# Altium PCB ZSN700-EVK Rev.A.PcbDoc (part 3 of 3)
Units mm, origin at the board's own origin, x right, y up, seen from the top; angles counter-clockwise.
Board outline 122.05 x 75.06 mm, 2 copper layers (Top Layer, Bottom Layer), stack 0 mm thick; 172 components, 135 nets, 573 pads, 599 vias.
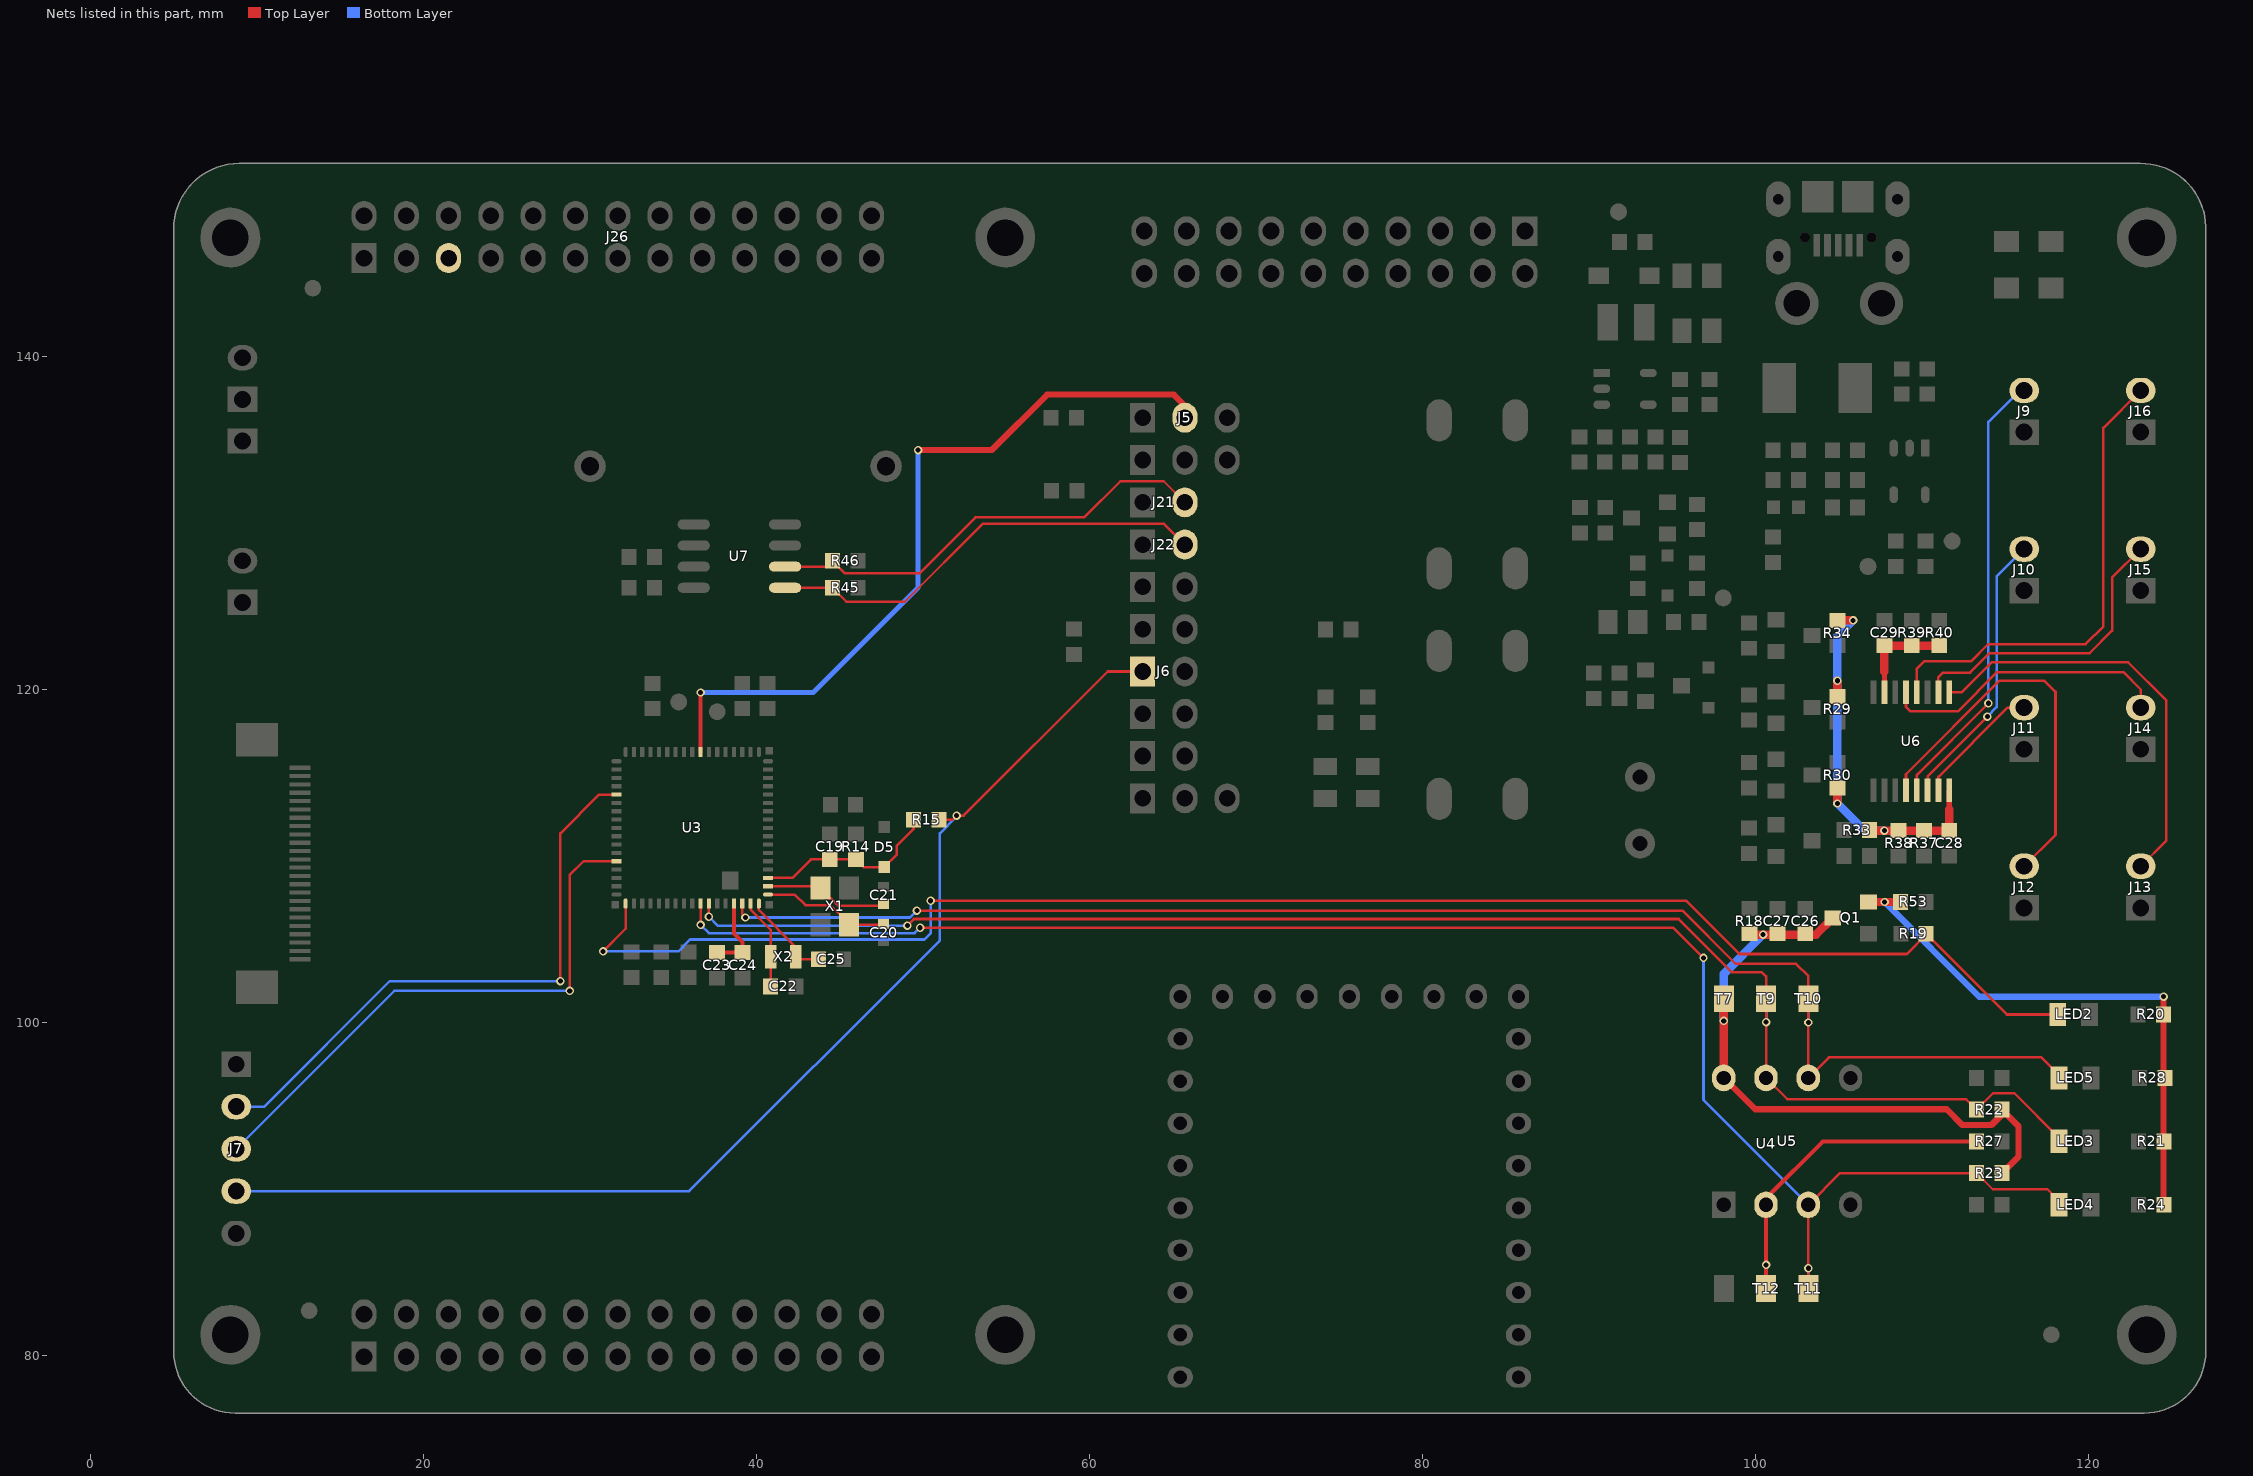
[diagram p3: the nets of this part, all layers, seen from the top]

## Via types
v1: diameter 0.508, hole 0.305, Top Layer to Bottom Layer, tented both sides, 599 vias

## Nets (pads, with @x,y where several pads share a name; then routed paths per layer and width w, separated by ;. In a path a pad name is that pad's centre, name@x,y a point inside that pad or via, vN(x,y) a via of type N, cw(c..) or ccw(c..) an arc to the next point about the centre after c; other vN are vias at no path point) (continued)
NRST: C19.1 D5.1 R14.1 R15.1 U3.37 | length 11.2
  Top Layer w0.152: U3.37@40.69,108.702 42.16,108.702 43.266,109.808 C19.1@44.399,109.808 R14.1@45.974,109.808 46.433,109.349 D5.1@47.676,109.349 48.438,110.111 48.438,110.636 49.44,111.639 R15.1@49.44,112.193
PB08: LED4.2 R23.1 T11.1 U3.27 U4.4 U5.3 | length 103.1
  Top Layer w0.152: v1(36.643,105.88) U3.27@36.643,107.152 ; v1(49.824,105.705) 95.078,105.705 v1(96.881,103.901) ; U4.4@103.178,84.037 v1(103.178,85.258) 103.178,89.063 U5.3@103.175,89.066 105.08,90.971 R23.1@113.284,90.971 114.254,90.001 117.529,90.001 118.237,89.293 LED4.2@118.237,89.066
  Bottom Layer w0.152: v1(36.643,105.88) 37.141,105.382 49.502,105.382 v1(49.824,105.705) ; v1(96.881,103.901) 96.881,95.36 U5.3@103.175,89.066 ; T11.1@103.178,84.037 v1(103.178,85.258)
PB09: LED3.2 R22.1 T9.1 U3.28 U4.2 U5.7 | length 93.7
  Top Layer w0.152: v1(37.143,106.369) U3.28@37.143,107.152 ; v1(49.062,105.84) 49.455,106.232 95.385,106.232 98.585,103.032 100.392,103.032 100.638,102.786 U4.2@100.638,101.437 v1(100.638,100.04) 100.638,96.69 U5.7@100.635,96.686 101.915,95.406 112.66,95.406 R22.1@113.284,94.781 114.27,95.767 115.548,95.767 118.237,93.078 LED3.2@118.237,92.876
  Bottom Layer w0.152: v1(37.143,106.369) 37.672,105.84 v1(49.062,105.84) ; v1(100.638,100.04) T9.1@100.638,101.437
PC13: LED5.2 T10.1 U3.32 U4.3 U5.6 | length 90.3
  Top Layer w0.152: U3.32@39.143,107.152 39.143,106.513 v1(39.334,106.322) ; v1(49.637,106.74) 95.617,106.74 98.818,103.54 102.45,103.54 103.178,102.811 U4.3@103.178,101.437 v1(103.178,100.015) U5.6@103.178,96.69 ; U5.6@103.175,96.686 U5.6@103.178,96.69 ; LED5.2@118.237,96.686 118.237,96.863 117.179,97.921 104.41,97.921 U5.6@103.178,96.69
  Bottom Layer w0.152: v1(39.334,106.322) 49.219,106.322 v1(49.637,106.74) ; v1(103.178,100.015) T10.1@103.178,101.437
PD02: LED2.2 R19.1 U3.18 | length 97.1
  Top Layer w0.152: v1(30.789,104.29) 32.143,105.645 U3.18@32.143,107.152 ; v1(50.459,107.33) 95.84,107.33 99.04,104.13 109.099,104.13 110.254,105.285 R19.1@110.254,105.349 115.107,100.496 LED2.2@118.161,100.496
  Bottom Layer w0.152: v1(30.789,104.29) 35.31,104.29 36.021,105.001 50.087,105.001 50.459,105.374 v1(50.459,107.33)
PVPP: R27.2 T12.1 U4.5 U5.2 | length 20.9
  Top Layer w0.152: U5.2@100.635,89.066 U5.2@100.638,89.063
  Top Layer w0.254: U5.2@100.635,89.066 100.635,89.463 104.049,92.876 R27.2@113.284,92.876 ; U4.5@100.638,84.037 v1(100.638,85.461) U5.2@100.638,89.063
  Bottom Layer w0.254: T12.1@100.638,84.037 v1(100.638,85.461)
RESETB: J6.1 J7.4 R15.2 | length 72.3
  Top Layer w0.152: R15.2@50.964,112.193 51.765,112.193 v1(52.019,112.447) 52.446,112.447 61.098,121.098 J6.1@63.191,121.098
  Bottom Layer w0.152: J7.4@8.755,89.886 35.956,89.886 51.015,104.945 51.015,111.38 52.019,112.384 v1(52.019,112.447)
RUN_AWORKS: J26.5
SAM_VCC: C26.1 C27.1 Q1.3 R18.1 R22.2 R23.2 T7.1 U4.1 U5.8 | length 39.4
  Top Layer w0.381: U5.8@98.095,96.686 99.985,94.797 111.481,94.797 112.415,93.862 114.177,93.862 114.808,94.494 R22.2@114.808,94.781 115.799,93.791 115.799,91.962 R23.2@114.808,90.971
  Top Layer w0.508: U5.8@98.095,96.686 98.098,96.69 v1(98.098,100.117) U4.1@98.098,101.437 ; R18.1@99.64,105.298 v1(100.463,105.298) 103.643,105.298 Q1.3@104.644,106.299
  Bottom Layer w0.508: v1(98.098,100.117) T7.1@98.098,101.437 98.098,102.934 v1(100.463,105.298)
SCL: J21.2 R46.1 U7.2 | length 27.3
  Top Layer w0.152: U7.2@41.723,127.394 44.212,127.394 R46.1@44.568,127.75 45.327,126.99 49.795,126.99 53.156,130.351 59.684,130.351 61.859,132.526 64.464,132.526 J21.2@65.731,131.258
SDA: J22.2 R45.1 U7.1 | length 26.8
  Top Layer w0.152: U7.1@41.723,126.124 R45.1@44.568,126.124 45.404,125.288 48.906,125.288 53.579,129.96 64.49,129.96 J22.2@65.731,128.718
SWCLK: J7.3 U3.13 | length 34.1
  Top Layer w0.152: v1(28.784,101.916) 28.784,108.873 29.613,109.702 U3.13@31.59,109.702
  Bottom Layer w0.152: J7.3@8.755,92.426 18.246,101.916 v1(28.784,101.916)
SWDIO: J7.2 U3.5 | length 35.8
  Top Layer w0.152: v1(28.225,102.496) 28.225,111.375 30.553,113.702 U3.5@31.59,113.702
  Bottom Layer w0.152: J7.2@8.755,94.966 10.446,94.966 17.976,102.496 v1(28.225,102.496)
TX1: J9.2 U6.13 | length 26.8
  Top Layer w0.152: U6.13@109.693,113.956 109.693,114.89 v1(113.995,119.191)
  Bottom Layer w0.152: v1(113.995,119.191) 113.995,136.082 115.889,137.977 J9.2@116.143,137.977
TX2: J10.2 U6.14 | length 16.9
  Top Layer w0.152: U6.14@110.343,113.956 110.343,114.804 v1(113.933,118.393)
  Bottom Layer w0.152: v1(113.933,118.393) 114.492,118.952 114.492,126.8 J10.2@116.143,128.451
TX3: J11.2 U6.15 | length 7.7
  Top Layer w0.152: U6.15@110.993,113.956 110.993,114.768 115.151,118.925 J11.2@116.143,118.925
TX4: J12.2 U6.12 | length 23.8
  Top Layer w0.152: U6.12@109.043,113.956 109.043,114.926 114.67,120.552 117.339,120.552 118.022,119.869 118.022,111.279 J12.2@116.143,109.4
TX5: J13.2 U6.1 | length 25.3
  Top Layer w0.152: U6.1@111.643,119.856 112.398,119.856 114.187,121.645 122.391,121.645 124.677,119.359 124.677,110.934 J13.2@123.143,109.4
TX6: J14.2 U6.5 | length 17.6
  Top Layer w0.152: U6.5@109.043,119.856 109.043,118.978 109.323,118.698 112.155,118.698 114.517,121.06 122.098,121.06 123.143,120.015 J14.2@123.143,118.925
TX7: J15.2 U6.2 | length 18.1
  Top Layer w0.152: U6.2@110.993,119.856 110.993,120.762 111.266,121.035 112.892,121.035 114.06,122.203 120.08,122.203 121.426,123.55 121.426,126.734 J15.2@123.143,128.451
TX8: J16.2 U6.4 | length 28.8
  Top Layer w0.152: U6.4@109.693,119.856 109.693,121.269 110.127,121.703 112.95,121.703 113.984,122.737 119.826,122.737 120.893,123.804 120.893,135.727 J16.2@123.143,137.977
VCAP: C23.1 C24.1 U3.31 | length 4.7
  Top Layer w0.254: C23.1@37.639,104.226 C24.1@39.163,104.226 39.163,104.842 38.643,105.362 U3.31@38.643,107.152
VCC_4051: C28.1 R29.2 R30.2 R33.2 R34.2 R37.2 R38.2 U6.16 | length 24.9
  Top Layer w0.305: 111.643,112.817 U6.16@111.643,113.956
  Top Layer w0.508: v1(104.923,113.17) R30.2@104.923,114.112 ; R29.2@104.923,119.598 v1(104.923,120.54) ; R34.2@104.923,124.17 v1(105.865,124.17) ; R33.2@106.856,111.572 106.885,111.543 v1(107.74,111.543) R38.2@108.595,111.543 R37.2@110.119,111.543 C28.1@111.643,111.543 111.643,112.817
  Bottom Layer w0.508: v1(105.865,124.17) 104.923,123.229 v1(104.923,120.54) v1(104.923,113.17) 106.551,111.543 v1(107.74,111.543)
VCC_ANT: J5.2 U3.59 | length 45.9
  Top Layer w0.254: U3.59@36.643,116.252 v1(36.643,119.837)
  Top Layer w0.381: v1(49.713,134.398) 54.125,134.398 57.457,137.73 65.059,137.73 65.731,137.058 J5.2@65.731,136.338
  Bottom Layer w0.305: v1@36.624,119.837 v1(36.643,119.837) 43.405,119.837 49.713,126.146 v1(49.713,134.398)
VDD_3V3_SAM: Q1.2 R20.2 R21.2 R24.2 R28.2 R53.2 | length 33.5
  Top Layer w0.381: R24.2@124.512,89.1 R20.2@124.512,100.496 v1(124.512,101.57)
  Top Layer w0.508: Q1.2@106.803,107.249 106.808,107.254 v1(107.758,107.254) R53.2@108.708,107.254 ; R24.2@124.512,89.1 R24.2@124.546,89.066
  Bottom Layer w0.381: v1(107.758,107.254) 113.442,101.57 v1(124.512,101.57)
VEE_4051: C29.1 R39.2 R40.2 U6.7 | length 6.1
  Top Layer w0.305: U6.7@107.743,119.856 107.743,121.096
  Top Layer w0.508: 107.743,121.096 C29.1@107.743,122.65 R39.2@109.394,122.65 R40.2@111.045,122.65
XTHI: C20.2 U3.35 X1.1 | length 7.8
  Top Layer w0.152: U3.35@40.69,107.702 42.298,107.702 42.939,107.061 44.43,107.061 X1.1@45.599,105.892 ; X1.1@45.549,105.892 X1.1@45.599,105.892 ; X1.1@45.664,105.888 45.603,105.888 X1.1@45.599,105.892 ; C20.2@47.631,105.918 47.605,105.892 X1.1@45.599,105.892
XTHO: C21.1 U3.36 X1.3 | length 7.6
  Top Layer w0.152: U3.36@40.69,108.202 43.739,108.202 X1.3@43.849,108.092 X1.3@43.854,108.088 ; X1.3@43.964,108.088 X1.3@43.854,108.088 ; C21.1@47.631,107.137 47.529,107.035 44.906,107.035 X1.3@43.854,108.088
XTLI: C22.1 U3.33 X2.2 | length 5.5
  Top Layer w0.152: U3.33@39.643,107.152 39.643,106.796 40.851,105.588 X2.2@40.851,103.973 40.855,103.969 C22.1@40.855,102.185
XTLO: C25.1 U3.34 X2.1 | length 5.5
  Top Layer w0.152: U3.34@40.143,107.152 40.143,106.763 42.351,104.555 X2.1@42.351,103.973 42.515,103.81 C25.1@43.719,103.81
pads on no net: HOLE1.1 HOLE2.1 HOLE3.1 HOLE5.1 HOLE6.1 J1.0 J1.2 J1.3 J1.4 J28.13 J28.14 J28.15 J28.16 J28.17 J28.18 J28.19 J28.20 J28.21 J28.22 J28.23 J28.24 MARK3.0 MARK4.0 MARK5.0 U3. U7.3
copper on no net:
  other v1: 0,151.614

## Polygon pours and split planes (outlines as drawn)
GND on Top Layer "GND" (solid, remove dead copper, pour order 0): 5,80.24 ccw(c8.683,80.24) 8.683,76.557 123.364,76.557 ccw(c123.364,80.24) 127.047,80.24 127.047,147.804 ccw(c123.174,147.74) 123.11,151.614 8.937,151.614 ccw(c8.937,147.677) 5,147.677
GND on Bottom Layer "GND" (solid, remove dead copper, pour order 2): 5,80.24 ccw(c8.683,80.24) 8.683,76.557 123.364,76.557 ccw(c123.364,80.24) 127.047,80.24 127.047,147.804 ccw(c123.174,147.74) 123.11,151.614 8.937,151.614 ccw(c8.937,147.677) 5,147.677

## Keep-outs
Keep-Out Layer:
  the board outline again, w0.127

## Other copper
Top Layer:
  rectangle net GND: 106.756,126.668 111.582,127.994
  pour cut-out: 108.307,134.512 110.207,134.512 110.207,136.224 108.307,136.224
  pour cut-out: 95.885,143.768 95.885,142.625 96.85,142.625 96.85,143.768
  pour cut-out: 92.982,138.383 91.491,138.383 91.237,138.637 91.323,138.637 91.752,139.066 92.688,139.066 92.982,138.772
  pour cut-out: 119.092,101.577 119.092,99.415 119.23,99.415 119.23,101.577
  pour cut-out: 119.125,90.147 119.125,87.985 119.263,87.985 119.263,90.147
  pour cut-out: 119.125,93.957 119.125,91.795 119.263,91.795 119.263,93.957
  pour cut-out: 119.125,97.767 119.125,95.605 119.263,95.605 119.263,97.767
  region net GND: 109.168,126.289 108.788,126.668 106.756,126.668 106.756,127.994 111.582,127.994 111.582,126.367 111.504,126.289
  pour cut-out: 73.091,116.269 77.793,116.269 77.793,114.355 73.091,114.355
  pour cut-out: 94.281,120.357 94.281,119.892 94.005,119.892 94.005,120.357
  pour cut-out: 104.067,121.815 101.905,121.815 101.905,122.432 104.067,122.432
  pour cut-out: 102.129,119.05 102.129,116.437 101.651,116.437 101.651,119.05
  pour cut-out: 102.129,114.986 101.6,114.986 101.6,112.729 102.129,112.729
  pour cut-out: 102.51,111.775 102.51,111.256 101.879,111.256 101.879,111.775
  pour cut-out: 112.453,90.505 112.878,90.505 112.878,89.412 112.453,89.412
  region net 5.0V_AWORKS: 109.953,135.426 108.505,136.874 108.505,138.181 110.703,138.181 110.994,137.89 110.994,134.283 110.715,134.004 109.953,134.004
  region net 3.3V: 109.699,130.132 109.179,129.612 109.179,128.529 109.343,128.365 110.709,128.365 110.918,128.575 110.918,132.208 110.664,132.462 109.935,132.462 109.699,132.226
  region net 5.0V_AWORKS: 106.071,146.801 106.071,142.889 107.023,141.937 108.255,143.168 108.255,144.311 106.477,146.089 106.477,146.801
  region net 5.0V_AWORKS: 107.874,144.692 104.928,141.746 104.928,136.692 104.982,136.638 107.161,136.638 107.341,136.818 107.341,140.73 109.043,142.432 109.043,143.524
  region net GND: 103.877,146.801 103.877,142.575 101.969,140.666 100.661,141.975 100.661,143.279 103.471,146.089 103.471,146.801
  region net NetC10_1: 92.702,139.052 92.982,138.772 94.186,138.772 94.821,138.137 97.797,138.137 97.899,138.238 97.899,139.544 97.757,139.686 96.766,139.686 96.258,140.194 96.258,142.189 96.157,142.291 92.919,142.291 92.702,142.074
  region net -5V_IN: 91.752,139.066 91.483,138.797 89.934,138.797 89.705,139.026 89.705,145.376 89.832,145.503 91.559,145.503 91.752,145.31
  region net NetC8_1: 92.906,145.909 92.906,147.56 96.081,147.56 96.208,147.433 96.208,144.131 96.081,144.004 93.083,144.004 92.906,144.182
  region net 8V: 92.131,148.017 92.36,147.789 92.36,146.265 92.131,146.036 90.455,146.036 90.455,148.017
Bottom Layer:
  pour cut-out: 62.06,112.783 62.06,111.174 63.123,111.174 63.123,112.783
Multi-Layer:
  pour cut-out: 99.06,151.614 99.06,141.482 99.72,140.821 111.023,140.821 111.506,141.304 111.506,144.377 111.897,144.769 118.898,144.769 120.904,142.762 127.047,142.762 127.047,149.918 125.351,151.614
  pour cut-out: 5,76.557 11.9,76.557 11.9,81.258 ccw(c8.4,81.258) 8.4,84.758 5,84.758
  pour cut-out: 5,143.658 8.4,143.658 ccw(c8.4,147.158) 11.9,147.158 11.9,151.614 5,151.614
  pour cut-out: 51.44,147.158 ccw(c54.94,147.158) 54.94,143.658 ccw(c54.94,147.158) 58.44,147.158 58.44,151.614 51.44,151.614
  pour cut-out: 51.44,76.557 51.44,81.258 cw(c54.94,81.258) 54.94,84.758 cw(c54.94,81.258) 58.44,81.258 58.44,76.557
  pour cut-out: 120,76.557 120,81.258 cw(c123.5,81.258) 123.5,84.758 127.047,84.758 127.047,80.24 cw(c123.364,80.24) 123.364,76.557

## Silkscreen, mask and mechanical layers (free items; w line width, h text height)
Top Overlay:
  circle w0.127: c123.5,147.158 r3.5
  region: 87.41,142.436 88.655,143.68 88.655,141.191
  region: 16.455,136.505 17.7,135.26 15.211,135.26
  region: 14.906,85.806 13.661,84.562 13.661,87.051
  lines w0.127: 15.142,87.895 47.629,87.895 ; 15.218,140.625 47.705,140.625 ; 17.53,136.904 17.53,144.346 ; 17.631,84.173 17.631,91.616 ; 20.044,136.904 20.044,144.346 ; 20.121,84.173 20.121,91.616 ; 22.559,136.904 22.559,144.346 ; 22.61,84.173 22.61,91.616 ; 25.074,136.904 25.074,144.346 ; 25.099,84.173 25.099,91.616 ; 27.588,84.173 27.588,91.616 ; 27.588,136.904 27.588,144.346 ; 30.077,84.173 30.077,91.616 ; 30.103,136.904 30.103,144.346 ; 32.567,84.173 32.567,91.616 ; 32.617,136.904 32.617,144.346 ; 35.056,84.173 35.056,91.616 ; 35.132,136.904 35.132,144.346 ; 37.545,84.173 37.545,91.616 ; 37.647,136.904 37.647,144.346 ; 40.034,84.173 40.034,91.616 ; 40.161,136.904 40.161,144.346 ; 42.523,84.173 42.523,91.616 ; 42.676,136.904 42.676,144.346 ; 45.013,84.173 45.013,91.616 ; 45.47,136.904 45.47,144.27 ; 62.531,140.95 87.017,140.95 ; 64.538,137.851 64.538,144.074 ; 67.078,137.851 67.078,144.074 ; 69.618,137.851 69.618,144.074 ; 72.158,137.851 72.158,144.074 ; 74.698,137.851 74.698,144.074 ; 77.238,137.851 77.238,144.074 ; 79.778,137.851 79.778,144.074 ; 82.318,137.851 82.318,144.074 ; 84.858,137.851 84.858,144.074 ; 15.142,84.173 15.142,91.616 47.629,91.616 47.629,84.173 15.142,84.173 ; 15.218,136.904 47.705,136.904 47.705,144.346 15.218,144.346 15.218,136.904 ; 62.531,137.851 87.067,137.851 87.067,144.074 62.531,144.074 62.531,137.851
  text "POWER" at 110.867,149.328 h2.03
  text "8V" at 92.786,148.289 h0.89
  text "MiniPort" at 61.029,143.903 h2.03 r90
  text "5V" at 47.172,141.73 h0.89 r90
  text "UT2" at 36.935,141.425 h0.89 r90
  text "CS" at 16.86,141.403 h0.89 r90
  text "MOSI" at 19.349,141.403 h0.89 r90
  text "NC" at 21.889,141.403 h0.89 r90
  text "NC" at 24.429,141.403 h0.89 r90
  text "NC" at 26.969,141.403 h0.89 r90
  text "UT3" at 34.37,141.4 h0.89 r90
  text "UT1" at 39.475,141.4 h0.89 r90
  text "UT0" at 42.209,141.403 h0.89 r90
  text "LUT1" at 29.315,141.298 h0.89 r90
  text "3.3V" at 44.606,141.298 h0.89 r90
  text "GND" at 84.041,141.312 h0.76 r90
  text "3.3V" at 86.505,141.312 h0.76 r90
  text "LUT0" at 31.906,141.273 h0.89 r90
  text "PA10" at 63.903,141.28 h0.76 r90
  text "PB12" at 78.914,141.28 h0.76 r90
  text "PA09" at 66.214,141.255 h0.76 r90
  text "PB15" at 68.779,141.255 h0.76 r90
  text "PB13" at 71.243,141.255 h0.76 r90
  text "PC09" at 73.732,141.229 h0.76 r90
  text "PB14" at 76.298,141.229 h0.76 r90
  text "PC00" at 81.403,141.178 h0.76 r90
  text "ANT1" at 116.285,141.058 h1.27
  text "ANT8" at 123.285,141.058 h1.27
  text "TX1" at 14.447,139.524 h1.52 r90
  text "5V" at 86.432,138.511 h0.76 r90
  text "GND" at 83.918,138.359 h0.76 r90
  text "PA02" at 73.881,138.137 h0.76 r90
  text "PC08" at 78.889,138.13 h0.76 r90
  text "PC01" at 81.454,138.13 h0.76 r90
  text "PB07" at 63.903,138.105 h0.76 r90
  text "PA03" at 76.349,138.105 h0.76 r90
  text "PC03" at 68.754,138.08 h0.76 r90
  text "PB06" at 66.239,138.054 h0.76 r90
  text "PC02" at 71.243,138.054 h0.76 r90
  text "SCK" at 16.809,137.415 h0.89 r90
  text "MISO" at 19.349,137.415 h0.89 r90
  text "NC" at 21.889,137.415 h0.89 r90
  text "NC" at 24.429,137.415 h0.89 r90
  text "NC" at 26.969,137.415 h0.89 r90
  text "UR3" at 34.294,137.412 h0.89 r90
  text "UR2" at 36.885,137.412 h0.89 r90
  text "UR1" at 39.501,137.412 h0.89 r90
  text "UR0" at 41.939,137.412 h0.89 r90
  text "GND" at 44.555,137.412 h0.89 r90
  text "LUR1" at 29.265,137.386 h0.89 r90
  text "LUR0" at 31.855,137.386 h0.89 r90
  text "GND" at 47.172,137.386 h0.89 r90
  text "PWR_ANT" at 70.227,136.035 h1.52
  text "GND" at 14.447,135.688 h1.52 r90
  text "KEY" at 70.227,133.419 h1.52
  text "RX" at 14.447,133.047 h1.52 r90
  text "ANT2" at 116.285,131.532 h1.27
  text "ANT7" at 123.285,131.532 h1.27
  text "SCL" at 67.89,130.75 h1.52
  text "PWR" at 102.29,128.852 h1.27
  text "KEY/RES" at 78.998,128.538 h1.52 r90
  text "SDA" at 67.89,128.21 h1.52
  text "TX2" at 14.449,127.462 h1.52 r90
  text "GND" at 103.483,126.972 h0.89
  text "BEEP" at 67.89,125.67 h1.52
  text "3.3V" at 112.348,125.601 h0.89 r90
  text "GND" at 14.449,123.525 h1.52 r90
  text "BOOT0" at 67.89,123.257 h1.52
  text "-5V" at 98.523,122.14 h0.89 r90
  text "ANT3" at 116.285,122.006 h1.27
  text "ANT6" at 123.285,122.006 h1.27
  text "RST" at 67.89,120.59 h1.52
  text "ANT_TX2" at 35.814,119.943 h0.89 r90
  text "ANT_TX1" at 37.77,119.866 h0.89 r90
  text "LED1" at 67.89,118.05 h1.52
  text "LED0" at 67.89,115.51 h1.52
  text "ANT4" at 116.285,112.481 h1.27
  text "ANT5" at 123.285,112.481 h1.27
  text "RST" at 81.817,110.326 h1.52
  text "5V" at 63.852,107.829 h1.52 r90
  text "Vmic" at 66.214,107.829 h1.52 r90
  text "3.3VA" at 68.729,107.829 h1.52 r90
  text "LCD" at 15.418,104.957 h1.52 r90
  text "GND" at 65.909,103.522 h0.89 r90
  text "PC04" at 68.449,103.522 h0.89 r90
  text "PC05" at 70.989,103.522 h0.89 r90
  text "PA04" at 73.529,103.522 h0.89 r90
  text "PA08" at 76.069,103.522 h0.89 r90
  text "PA10" at 78.609,103.522 h0.89 r90
  text "PA09" at 81.149,103.522 h0.89 r90
  text "PA11" at 83.689,103.522 h0.89 r90
  text "PA12" at 86.229,103.522 h0.89 r90
  text "PB13" at 60.372,98.569 h0.89
  text "PA03" at 87.728,98.569 h0.89
  text "SPWR" at 117.764,98.185 h0.89
  text "3.3V" at 10.79,97.055 h0.89
  text "200313 Rev.A" at 44.987,96.696 h1.52
  text "PB14" at 60.372,96.029 h0.89
  text "PA02" at 87.728,96.029 h0.89
  text "ZSN700-EVK" at 20.554,94.884 h3.81
  text "SWDIO" at 10.79,94.515 h0.89
  text "P/N: 13.01.04767" at 43.793,94.511 h1.52
  text "SCLK" at 117.797,94.375 h0.89
  text "PB15" at 60.372,93.489 h0.89
  text "PA00" at 87.728,93.489 h0.89
  text "SWCLK" at 10.79,91.975 h0.89
  text "PB12" at 60.372,90.949 h0.89
  text "PA01" at 87.728,90.949 h0.89
  text "SRST" at 117.797,90.565 h0.89
  text "RST" at 10.79,89.435 h0.89
  text "NC" at 41.685,88.872 h0.89 r90
  text "NC" at 44.149,88.822 h0.89 r90
  text "NC" at 16.869,88.466 h0.89 r90
  text "AD0" at 39.247,88.415 h0.89 r90
  text "PF07" at 60.372,88.409 h0.89
  text "PF06" at 87.728,88.409 h0.89
  text "PC01" at 19.419,88.387 h0.89 r90
  text "PC10" at 31.754,88.39 h0.89 r90
  text "SCL" at 34.294,88.39 h0.89 r90
  text "AD2" at 36.758,88.39 h0.89 r90
  text "PC08" at 24.261,88.364 h0.89 r90
  text "PA11" at 29.333,88.372 h0.89 r90
  text "GND" at 46.791,88.364 h0.89 r90
  text "PC06" at 21.815,88.346 h0.89 r90
  text "PA08" at 26.844,88.245 h0.89 r90
  text "GND" at 10.79,86.895 h0.89
  text "SDATA" at 117.797,86.755 h0.89
  text "PB01" at 60.372,85.869 h0.89
  text "PB11" at 87.728,85.869 h0.89
  text "NC" at 44.251,84.834 h0.89 r90
  text "SDA" at 34.286,84.816 h0.89 r90
  text "5V" at 46.968,84.783 h0.89 r90
  text "GND" at 41.711,84.681 h0.89 r90
  text "AD1" at 39.348,84.656 h0.89 r90
  text "PC07" at 24.329,84.638 h0.89 r90
  text "PB00" at 16.86,84.552 h0.89 r90
  text "PC12" at 19.4,84.552 h0.89 r90
  text "PC09" at 26.844,84.562 h0.89 r90
  text "PA12" at 29.282,84.562 h0.89 r90
  text "PC11" at 31.746,84.562 h0.89 r90
  text "AD3" at 36.775,84.562 h0.89 r90
  text "PC00" at 21.764,84.486 h0.89 r90
  text "PB00" at 60.372,83.329 h0.89
  text "PB10" at 87.728,83.329 h0.89
  text "3.3V" at 60.372,80.789 h0.89
  text "PC12" at 87.728,80.789 h0.89
  text "SAM" at 113.243,79.11 h1.27 r90
  text "Vmic" at 60.372,78.249 h0.89
  text "GND" at 87.728,78.249 h0.89
  text "MicroPort" at 71.675,77.944 h2.03
Bottom Overlay:
  region: 14.906,85.806 13.661,87.051 13.661,84.562
  region: 16.455,136.505 15.211,135.26 17.7,135.26
  lines w0.127: 15.142,87.895 47.629,87.895 ; 15.218,140.625 47.705,140.625 ; 17.53,136.904 17.53,144.346 ; 17.631,84.173 17.631,91.616 ; 20.044,136.904 20.044,144.346 ; 20.121,84.173 20.121,91.616 ; 22.559,136.904 22.559,144.346 ; 22.61,84.173 22.61,91.616 ; 25.074,136.904 25.074,144.346 ; 25.099,84.173 25.099,91.616 ; 27.588,84.173 27.588,91.616 ; 27.588,136.904 27.588,144.346 ; 30.077,84.173 30.077,91.616 ; 30.103,136.904 30.103,144.346 ; 32.567,84.173 32.567,91.616 ; 32.617,136.904 32.617,144.346 ; 35.056,84.173 35.056,91.616 ; 35.132,136.904 35.132,144.346 ; 37.545,84.173 37.545,91.616 ; 37.647,136.904 37.647,144.346 ; 40.034,84.173 40.034,91.616 ; 40.161,136.904 40.161,144.346 ; 42.523,84.173 42.523,91.616 ; 42.676,136.904 42.676,144.346 ; 45.013,84.173 45.013,91.616 ; 45.47,136.904 45.47,144.27 ; 15.142,84.173 47.629,84.173 47.629,91.616 15.142,91.616 15.142,84.173 ; 15.218,136.904 15.218,144.346 47.705,144.346 47.705,136.904 15.218,136.904
  text "5V" at 46.232,141.577 h0.89 r270
  text "NC" at 26.064,141.45 h0.89 r270
  text "NC" at 23.651,141.425 h0.89 r270
  text "NC" at 21.06,141.374 h0.89 r270
  text "3.3V" at 43.641,141.171 h0.89 r270
  text "PB12" at 15.879,141.146 h0.89 r270
  text "PC10" at 30.916,141.095 h0.89 r270
  text "PC03" at 35.996,141.095 h0.89 r270
  text "PC04" at 28.325,141.069 h0.89 r270
  text "PC07" at 33.379,141.069 h0.89 r270
  text "PB06" at 40.999,141.069 h0.89 r270
  text "PB15" at 18.495,141.044 h0.89 r270
  text "PA02" at 38.485,140.993 h0.89 r270
  text "NC" at 23.448,137.59 h0.89 r270
  text "NC" at 25.963,137.564 h0.89 r270
  text "NC" at 21.01,137.488 h0.89 r270
  text "PB07" at 41.025,137.412 h0.89 r270
  text "GND" at 43.717,137.412 h0.89 r270
  text "PC11" at 30.89,137.386 h0.89 r270
  text "PB14" at 18.393,137.361 h0.89 r270
  text "PC06" at 33.354,137.361 h0.89 r270
  text "PA03" at 38.485,137.361 h0.89 r270
  text "GND" at 46.333,137.336 h0.89 r270
  text "PB13" at 15.904,137.31 h0.89 r270
  text "PC03" at 36.021,137.285 h0.89 r270
  text "PC05" at 28.401,137.183 h0.89 r270
  text "SVCC" at 97.677,102.943 h0.89 r270
  text "SRST" at 100.217,102.943 h0.89 r270
  text "SCLK" at 102.757,102.943 h0.89 r270
  text "NC" at 40.822,88.847 h0.89 r270
  text "NC" at 43.26,88.822 h0.89 r270
  text "GND" at 46.021,88.47 h0.89 r270
  text "NC" at 16.006,88.441 h0.89 r270
  text "PA09" at 33.379,88.441 h0.89 r270
  text "PA11" at 28.426,88.39 h0.89 r270
  text "PC04" at 38.409,88.39 h0.89 r270
  text "PC01" at 18.47,88.364 h0.89 r270
  text "PC10" at 30.789,88.364 h0.89 r270
  text "PC06" at 20.806,88.339 h0.89 r270
  text "PC00" at 35.869,88.339 h0.89 r270
  text "PA08" at 25.912,88.288 h0.89 r270
  text "PC08" at 23.358,88.263 h0.89 r270
  text "NC" at 43.387,84.808 h0.89 r270
  text "5V" at 46.079,84.783 h0.89 r270
  text "PC07" at 23.397,84.631 h0.89 r270
  text "GND" at 40.872,84.631 h0.89 r270
  text "PC11" at 31.043,84.605 h0.89 r270
  text "PC05" at 38.409,84.605 h0.89 r270
  text "PA12" at 28.503,84.58 h0.89 r270
  text "PB00" at 15.973,84.562 h0.89 r270
  text "PC12" at 18.47,84.529 h0.89 r270
  text "PC09" at 25.955,84.536 h0.89 r270
  text "PA10" at 33.405,84.529 h0.89 r270
  text "PC00" at 21.035,84.478 h0.89 r270
  text "PC01" at 35.843,84.478 h0.89 r270
  text "GND" at 97.685,78.821 h0.89 r270
  text "PVPP" at 100.225,78.821 h0.89 r270
  text "SDATA" at 102.765,78.821 h0.89 r270
Mechanical 1:
  lines w0.051: 4.5,-1.69 5,-1.19 ; 5,-4.19 5,-1.19 ; 5,3.937 0,3.937 0,147.677 5,147.677 ; 5,11.937 3.5,11.937 3.5,63.24 5,63.24 ; 5,71.24 3.5,71.24 3.5,80.24 5,80.24 ; 5,88.24 3.5,88.24 3.5,139.804 5,139.804 ; 5.5,-1.69 5,-1.19 ; 126.547,-1.563 127.047,-1.063 ; 127.047,-4.063 127.047,-1.063 ; 127.047,3.937 132.047,3.937 132.047,147.804 128.547,147.804 127.047,147.804 ; 127.047,11.937 128.547,11.937 128.547,63.24 127.047,63.24 ; 127.047,71.24 128.547,71.24 128.547,80.24 127.047,80.24 ; 127.047,88.24 128.547,88.24 128.547,139.804 127.047,139.804 ; 127.547,-1.563 127.047,-1.063
  lines w0.127: 5,3.81 ccw(c8.874,3.873) 8.937,0 123.11,0 ccw(c123.11,3.937) 127.047,3.937 127.047,71.374 ccw(c123.364,71.374) 123.364,75.057 8.683,75.057 ccw(c8.683,71.374) 5,71.374 5,3.81 ; 5,80.24 ccw(c8.683,80.24) 8.683,76.557 123.364,76.557 ccw(c123.364,80.24) 127.047,80.24 127.047,147.804 ccw(c123.174,147.74) 123.11,151.614 8.937,151.614 ccw(c8.937,147.677) 5,147.677 5,80.24
  text "F" at 73.732,82.12 h12.7
  text "F" at 58.315,69.494 h12.7 r180
  text "VCUT" at 126.547,-4.063 h0.51 r90
  text "VCUT" at 4.5,-4.19 h0.51 r90
Mechanical 2:
  drawing of 637 lines, arcs and shapes, not listed
  text "PCB加工工艺要求" at 186.331,172.471 h7.11
  text "151.61" at 157.248,167.874 h2.54
  text "mm x" at 165.934,167.747 h2.54
  text "132.05" at 173.021,167.747 h2.54
  text "mm" at 181.428,167.747 h2.54
  text "IPC-600E   IPC-6011/12" at 210.842,167.493 h2.54
  text "IPC-Ⅱ" at 244.751,167.467 h2.54
  text "IPC-Ⅲ" at 257.451,167.467 h2.54
  text "尺寸" at 143.372,167.039 h3.81
  text "验收标准" at 194.172,167.039 h3.81
  text "FR4 TG140" at 161.312,162.413 h2.54
  text "FR4 TG170" at 184.172,162.413 h2.54
  text "生益有胶材料" at 207.032,162.413 h2.54
  text "MEGTRON6" at 229.892,162.413 h2.54
  text "其他：" at 252.752,162.413 h2.54
  text "板材" at 143.335,161.954 h3.81
  text "单面" at 161.312,157.333 h2.54
  text "2" at 179.092,157.333 h2.54
  text "4" at 196.872,157.333 h2.54
  text "6" at 214.652,157.333 h2.54
  text "8" at 232.432,157.333 h2.54
  text "10" at 250.212,157.333 h2.54
  text "板层" at 143.335,156.868 h3.81
  text "0.4mm" at 161.312,152.253 h2.54
  text "0.6mm" at 175.282,152.253 h2.54
  text "0.8mm" at 189.252,152.253 h2.54
  text "1.0mm" at 203.222,152.253 h2.54
  text "1.2mm" at 217.192,152.253 h2.54
  text "1.4mm" at 231.162,152.253 h2.54
  text "1.6mm" at 245.132,152.253 h2.54
  text "1.8mm" at 259.102,152.253 h2.54
  text "2.0mm" at 273.072,152.253 h2.54
  text "板厚" at 143.335,151.783 h3.81
  text "1/2OZ" at 192.554,147.173 h2.54
  text "1OZ" at 205.254,147.173 h2.54
  text "2OZ" at 217.954,147.173 h2.54
  text "（完成铜厚）" at 167.237,146.849 h3.3
  text "外层" at 160.221,146.69 h3.81
  text "铜厚" at 143.332,146.658 h3.81
  text "白色" at 172.742,142.093 h2.54
  text "其他：" at 190.522,142.093 h2.54
  text "丝印颜色" at 143.332,141.597 h3.81
  text "绿色" at 172.742,137.013 h2.54
  text "黑色" at 190.522,137.013 h2.54
  text "红色" at 208.302,137.013 h2.54
  text "蓝色" at 226.082,137.013 h2.54
  text "黄色" at 243.862,137.013 h2.54
  text "其他：" at 261.642,137.013 h2.54
  text "（亮光）" at 157.057,136.693 h3.3
  text "阻焊颜色" at 143.332,136.512 h3.81
  text "沉镍金" at 172.742,131.933 h2.54
  text "无铅喷锡" at 190.522,131.933 h2.54
  text "电镀镍金" at 208.302,131.933 h2.54
  text "电镀软金" at 226.082,131.933 h2.54
  text "化学沉锡" at 243.862,131.933 h2.54
  text "光板" at 261.642,131.933 h2.54
  text "OSP" at 274.85,131.933 h2.54
  text "表面处理工艺" at 143.332,131.401 h3.81
  text "无" at 172.742,126.878 h2.54
  text "按键镀硬金" at 183.41,126.878 h2.54
  text "金手指" at 201.698,126.878 h2.54
  text "半孔工艺" at 219.224,126.878 h2.54
  text "FPCB补强" at 236.75,126.878 h2.54
  text "树脂塞孔" at 254.276,126.878 h2.54
  text "电镀填孔" at 271.802,126.878 h2.54
  text "特殊工艺" at 143.332,126.341 h3.81
  text "是，但双面开窗除外" at 172.742,121.773 h2.54
  text "否" at 201.825,121.773 h2.54
  text "按文件" at 219.605,121.773 h2.54
  text "是否阻焊塞孔" at 143.335,121.245 h3.81
  text "非拼板" at 172.742,116.693 h2.54
  text "拼板" at 190.522,116.693 h2.54
  text "分成单板交货" at 208.302,116.693 h2.54
  text "交货方式" at 143.332,116.185 h3.81
  text "Gerber输出：英制、相对零点、抑制前导零、精度2:5" at 143.405,111.765 h3.05
  text "Ver 19.01.16" at 262.658,110.063 h3.05
  text "NC Drill输出：英制、相对零点、抑制前导零、精度2:4" at 143.405,108.209 h3.05
  text "R" at 271.573,104.92 h0.64
  text "其他说明" at 143.278,103.764 h3.81
  text "94V-0" at 273.351,103.51 h1.17
  text "标识样式>>>" at 251.482,102.113 h3.05
  text "CTI>=175" at 269.389,101.351 h2.2
  text "1." at 142.643,100.335 h3.05
  text "机械1层(*.GM1)为外形铣边；若存在工艺副边，请在副边上增加分流点" at 145.818,100.335 h3.05
  text "2." at 142.64,97.033 h3.05
  text "请用供应商UL认证号，防火等级，CTI等级，生产周期替换板上的UR标识，且保持其位置、方向一致；" at 145.818,97.033 h3.05
  text "禁止添加文件中不存在的元素，包括供应商LOGO、无铅、光学基准点等" at 145.818,93.731 h3.05
  text "3." at 142.643,90.429 h3.05
  text "若焊盘开窗与丝印油冲突，焊盘处需将丝印油掏开，不允许上盘" at 145.818,90.429 h3.05
  text "4." at 142.643,87.381 h3.05
  text "若存在V-CUT，无特别说明时，须为双面V-CUT，角度30（+-5°），余量按以下表格执行" at 145.818,87.381 h3.05
  text "PCB厚度（mm）" at 156.765,82.936 h3.05
  text "筋厚" at 148.256,82.555 h3.05
  text "（余量）" at 146.986,79.507 h3.05
  text "0.6" at 156.765,79.38 h3.05
  text "0.8" at 162.851,79.38 h3.05
  text "1" at 170.377,79.38 h3.05
  text "1.2" at 175.053,79.38 h3.05
  text "1.6" at 181.149,79.38 h3.05
  text "2" at 188.388,79.38 h3.05
  text "2.5" at 193.326,79.38 h3.05
  text "3" at 200.58,79.38 h3.05
  text "0.16" at 156.006,75.888 h3.05
  text "0.2" at 162.864,75.888 h3.05
  text "0.3" at 168.96,75.888 h3.05
  text "0.3" at 174.951,75.888 h3.05
  text "0.4" at 181.061,75.888 h3.05
  text "0.5" at 187.252,75.888 h3.05
  text "0.5" at 193.344,75.888 h3.05
  text "最小值" at 146.859,75.824 h3.05
  text "0.5" at 199.412,75.824 h3.05
  text "0.32" at 156.017,72.395 h3.05
  text "0.4" at 162.857,72.395 h3.05
  text "0.45" at 168.195,72.395 h3.05
  text "0.5" at 174.944,72.395 h3.05
  text "0.6" at 181.124,72.395 h3.05
  text "0.7" at 187.26,72.395 h3.05
  text "0.8" at 193.349,72.395 h3.05
  text "0.8" at 199.44,72.395 h3.05
  text "最大值" at 146.859,72.268 h3.05
  text "5." at 142.643,67.95 h3.05
  text "PCB做完后，请高温烘烤进行应力释放，再整平（或重物压板烘烤），防止翘曲" at 145.818,67.95 h3.05
  text "我司生产使用无铅工艺制程" at 145.691,64.521 h3.05
  text "6." at 142.643,64.394 h3.05
  text "7." at 142.643,60.711 h3.05
  text "未尽事项请参照我司《PCB质量补充协议》" at 145.691,60.711 h3.05
Mechanical 3:
  circle w0.178: c8.4,147.158 r1.6
  circle w0.178: c8.4,147.158 r2.8
  lines w0.152: 8.4,82.682 8.4,81.258 9.951,81.258 ; 8.4,148.582 8.4,147.158 9.951,147.158 ; 54.94,148.582 54.94,147.158 56.491,147.158 ; 123.5,82.682 123.5,81.258 125.051,81.258 ; 123.5,148.582 123.5,147.158 125.051,147.158
Mechanical 15:
  lines w0.051: 0,0.5 0,0 0.437,0 ; 0,151.114 0,151.614 0.437,151.614 ; 131.61,0 132.047,0 132.047,0.5 ; 131.61,151.614 132.047,151.614 132.047,151.114

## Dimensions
0,151.614 to 0,0 on Mechanical 1
0,151.614 to 132.047,151.614 on Mechanical 1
